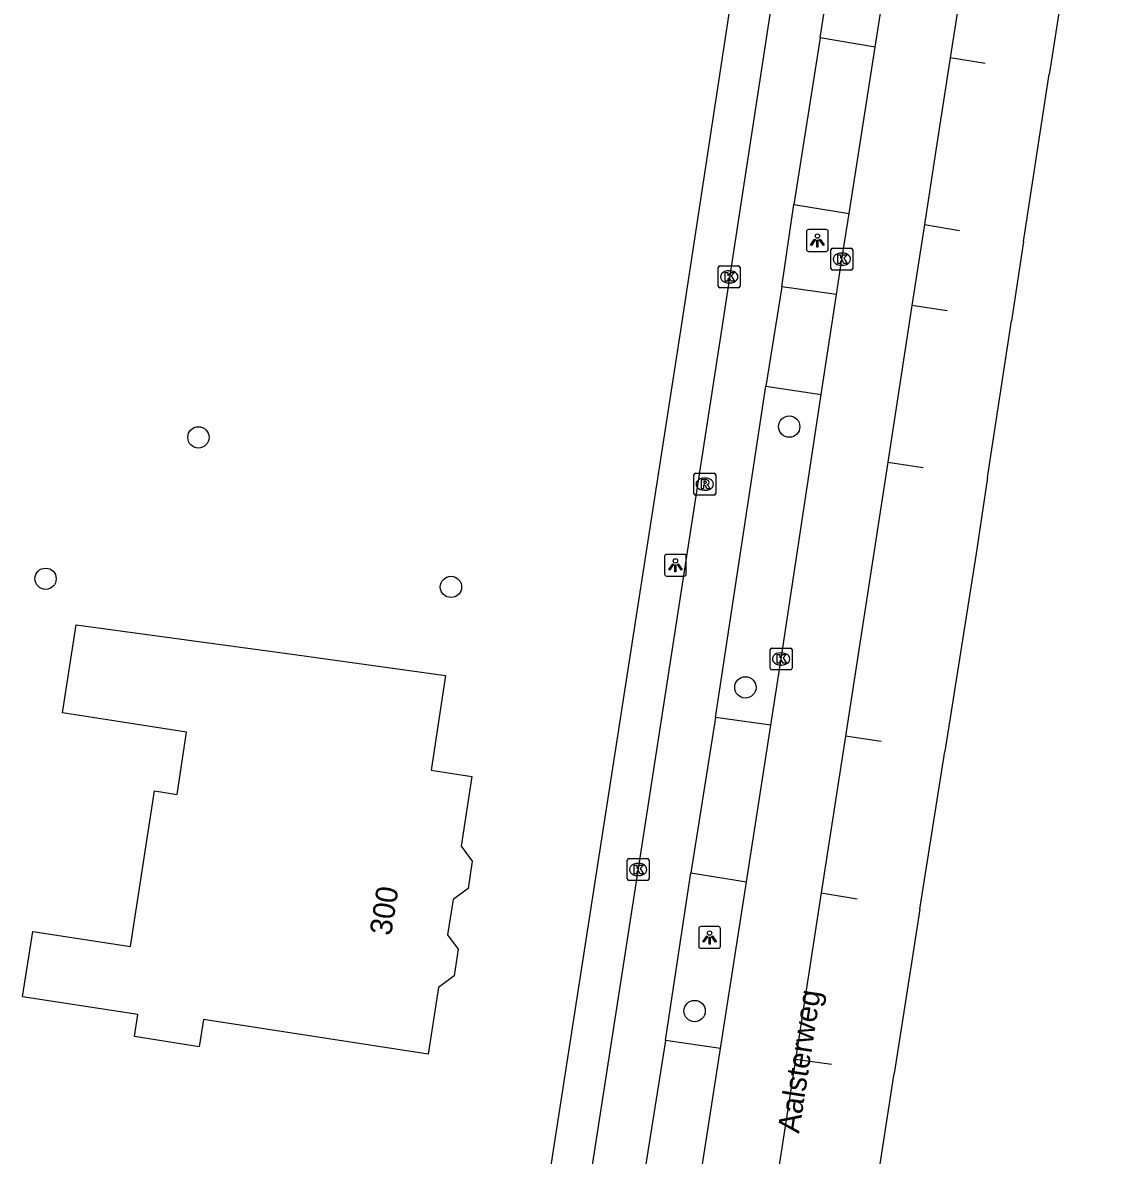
# Model space of a CAD drawing. Extents: x 161094 to 161705, y 379509 to 380907.
# Drawn here: x 161629.9 to 161680.5, y 380637.7 to 380689.7 of the extents above; entities that cross this region are included whole.
import ezdxf

# ---------------------------------------------------------------- set-up
doc = ezdxf.new("R2010")
doc.units = 0
for name, color, linetype in [('IMGEO_Boom', 7, 'Continuous'), ('IMGEO_Fietspad_gesloten', 7, 'Continuous'), ('IMGEO_Kolk', 7, 'Continuous'), ('IMGEO_Lichtpunt', 7, 'Continuous'), ('IMGEO_Openbare_ruimte_label', 7, 'Continuous'), ('IMGEO_OVBaan_gesloten', 7, 'Continuous'), ('IMGEO_Pand', 7, 'Continuous'), ('IMGEO_Pand_nummerreeks', 7, 'Continuous'), ('IMGEO_Rijbaan_lokaal_open', 7, 'Continuous'), ('IMGEO_Rijbaan_regionaal_gesloten', 7, 'Continuous'), ('IMGEO_Rioolput', 7, 'Continuous'), ('IMGEO_Voetpad_open', 7, 'Continuous')]:
    doc.layers.add(name, color=color, linetype=linetype)

msp = doc.modelspace()

# ---------------------------------------------------------------- linework, layer by layer
at = {"layer": 'IMGEO_Boom'}
for centre in [(161665.082, 380671.126), (161637.988, 380670.632), (161630.975, 380664.146), (161649.57, 380663.774), (161663.073, 380659.164), (161660.744, 380644.315)]:
    msp.add_circle(centre, 0.489, dxfattribs=at)
at = {"layer": 'IMGEO_Fietspad_gesloten'}
for points in [[(161669.451, 380724.595), (161665.616, 380699.327), (161661.966, 380675.456), (161658.261, 380651.539), (161654.372, 380626.519), (161650.679, 380602.47), (161649.98, 380598.059)], [(161666.5, 380688.955), (161668.286, 380700.544), (161669.904, 380711.432)], [(161664.743, 380677.545), (161665.3, 380681.309)], [(161661.709, 380657.778), (161664.016, 380672.987)], [(161659.406, 380642.973), (161660.571, 380650.65)]]:
    msp.add_lwpolyline(points, dxfattribs=at)
at = {"layer": 'IMGEO_Kolk'}
for p, q in [((161666.997, 380678.381), (161666.997, 380679.233)), ((161667.072, 380679.307), (161667.924, 380679.307)), ((161667.485, 380679.087), (161667.51, 380679.087)), ((161667.998, 380679.233), (161667.998, 380678.381)), ((161661.906, 380678.494), (161662.758, 380678.494)), ((161667.508, 380678.527), (161667.483, 380678.527)), ((161661.831, 380677.568), (161661.831, 380678.42)), ((161662.319, 380678.274), (161662.344, 380678.274)), ((161662.832, 380678.42), (161662.832, 380677.568)), ((161667.924, 380678.307), (161667.072, 380678.307)), ((161662.758, 380677.494), (161661.906, 380677.494)), ((161662.342, 380677.714), (161662.317, 380677.714)), ((161664.211, 380660.043), (161664.211, 380660.895)), ((161664.286, 380660.969), (161665.138, 380660.969)), ((161665.212, 380660.895), (161665.212, 380660.043)), ((161664.699, 380660.749), (161664.724, 380660.749)), ((161665.138, 380659.969), (161664.286, 380659.969)), ((161664.722, 380660.189), (161664.697, 380660.189)), ((161657.654, 380650.383), (161657.654, 380651.235)), ((161657.729, 380651.309), (161658.581, 380651.309)), ((161658.142, 380651.089), (161658.167, 380651.089)), ((161658.655, 380651.235), (161658.655, 380650.383)), ((161658.165, 380650.529), (161658.14, 380650.529)), ((161658.581, 380650.309), (161657.729, 380650.309))]:
    msp.add_line(p, q, dxfattribs=at)
for points in [[(161666.997, 380678.381), (161666.997, 380679.233)], [(161667.072, 380679.307), (161667.924, 380679.307)], [(161667.318, 380679.007), (161667.441, 380679.007), (161667.441, 380678.856), (161667.571, 380679.007), (161667.735, 380679.007), (161667.589, 380678.856), (161667.742, 380678.607), (161667.59, 380678.607), (161667.505, 380678.771), (161667.441, 380678.704), (161667.441, 380678.607), (161667.318, 380678.607), (161667.318, 380679.007)], [(161667.998, 380679.233), (161667.998, 380678.381)], [(161661.906, 380678.494), (161662.758, 380678.494)], [(161661.831, 380677.568), (161661.831, 380678.42)], [(161662.152, 380678.194), (161662.275, 380678.194), (161662.275, 380678.043), (161662.405, 380678.194), (161662.569, 380678.194), (161662.423, 380678.043), (161662.576, 380677.794), (161662.424, 380677.794), (161662.339, 380677.958), (161662.275, 380677.891), (161662.275, 380677.794), (161662.152, 380677.794), (161662.152, 380678.194)], [(161662.832, 380678.42), (161662.832, 380677.568)], [(161667.924, 380678.307), (161667.072, 380678.307)], [(161662.758, 380677.494), (161661.906, 380677.494)], [(161664.211, 380660.043), (161664.211, 380660.895)], [(161664.286, 380660.969), (161665.138, 380660.969)], [(161665.212, 380660.895), (161665.212, 380660.043)], [(161664.532, 380660.669), (161664.655, 380660.669), (161664.655, 380660.518), (161664.785, 380660.669), (161664.949, 380660.669), (161664.803, 380660.518), (161664.956, 380660.269), (161664.804, 380660.269), (161664.719, 380660.433), (161664.655, 380660.366), (161664.655, 380660.269), (161664.532, 380660.269), (161664.532, 380660.669)], [(161665.138, 380659.969), (161664.286, 380659.969)], [(161657.654, 380650.383), (161657.654, 380651.235)], [(161657.729, 380651.309), (161658.581, 380651.309)], [(161657.975, 380651.009), (161658.098, 380651.009), (161658.098, 380650.858), (161658.228, 380651.009), (161658.392, 380651.009), (161658.246, 380650.858), (161658.399, 380650.609), (161658.247, 380650.609), (161658.162, 380650.773), (161658.098, 380650.706), (161658.098, 380650.609), (161657.975, 380650.609), (161657.975, 380651.009)], [(161658.655, 380651.235), (161658.655, 380650.383)], [(161658.581, 380650.309), (161657.729, 380650.309)]]:
    msp.add_lwpolyline(points, dxfattribs=at)
for centre, start, end in [((161667.074, 380679.231), 91.552, 178.448), ((161667.074, 380679.231), 91.552, 178.448), ((161667.922, 380679.231), 1.552, 88.448), ((161667.922, 380679.231), 1.552, 88.448), ((161661.908, 380678.418), 91.552, 178.448), ((161661.908, 380678.418), 91.552, 178.448), ((161662.756, 380678.418), 1.552, 88.448), ((161662.756, 380678.418), 1.552, 88.448), ((161667.074, 380678.383), 181.552, 268.448), ((161667.074, 380678.383), 181.552, 268.448), ((161667.922, 380678.383), 271.552, 358.448), ((161667.922, 380678.383), 271.552, 358.448), ((161661.908, 380677.57), 181.552, 268.448), ((161661.908, 380677.57), 181.552, 268.448), ((161662.756, 380677.57), 271.552, 358.448), ((161662.756, 380677.57), 271.552, 358.448), ((161664.288, 380660.893), 91.552, 178.448), ((161664.288, 380660.893), 91.552, 178.448), ((161665.136, 380660.893), 1.552, 88.448), ((161665.136, 380660.893), 1.552, 88.448), ((161664.288, 380660.045), 181.552, 268.448), ((161664.288, 380660.045), 181.552, 268.448), ((161665.136, 380660.045), 271.552, 358.448), ((161665.136, 380660.045), 271.552, 358.448), ((161657.731, 380651.233), 91.552, 178.448), ((161657.731, 380651.233), 91.552, 178.448), ((161658.579, 380651.233), 1.552, 88.448), ((161658.579, 380651.233), 1.552, 88.448), ((161657.731, 380650.385), 181.552, 268.448), ((161657.731, 380650.385), 181.552, 268.448), ((161658.579, 380650.385), 271.552, 358.448), ((161658.579, 380650.385), 271.552, 358.448)]:
    msp.add_arc(centre, 0.0765, start, end, dxfattribs=at)
for centre, major_axis, ratio, start_param, end_param in [((161667.484, 380678.807), (-0.387, 0.002), 0.722429, 4.712389, 7.853982), ((161667.509, 380678.807), (-0.39, 0.002), 0.717154, 1.570796, 4.712389), ((161662.318, 380677.994), (-0.387, 0.002), 0.722429, 4.712389, 7.853982), ((161662.343, 380677.994), (-0.39, 0.002), 0.717154, 1.570796, 4.712389), ((161664.698, 380660.469), (-0.387, 0.002), 0.722429, 4.712389, 7.853982), ((161664.723, 380660.469), (-0.39, 0.002), 0.717154, 1.570796, 4.712389), ((161658.141, 380650.809), (-0.387, 0.002), 0.722429, 4.712389, 7.853982), ((161658.166, 380650.809), (-0.39, 0.002), 0.717154, 1.570796, 4.712389)]:
    msp.add_ellipse(centre, major_axis=major_axis, ratio=ratio, start_param=start_param, end_param=end_param, dxfattribs=at)
at = {"layer": 'IMGEO_Lichtpunt'}
for p, q in [((161665.876, 380680.067), (161665.876, 380679.26)), ((161665.876, 380680.067), (161665.876, 380679.26)), ((161666.778, 380680.162), (161665.97, 380680.162)), ((161666.778, 380680.162), (161665.97, 380680.162)), ((161666.872, 380679.26), (161666.872, 380680.067)), ((161666.872, 380679.26), (161666.872, 380680.067)), ((161665.97, 380679.166), (161666.778, 380679.166)), ((161665.97, 380679.166), (161666.778, 380679.166)), ((161659.367, 380665.171), (161659.367, 380664.364)), ((161659.367, 380665.171), (161659.367, 380664.364)), ((161660.269, 380665.266), (161659.461, 380665.266)), ((161660.269, 380665.266), (161659.461, 380665.266)), ((161660.363, 380664.364), (161660.363, 380665.171)), ((161660.363, 380664.364), (161660.363, 380665.171)), ((161659.461, 380664.27), (161660.269, 380664.27)), ((161659.461, 380664.27), (161660.269, 380664.27)), ((161660.934, 380648.097), (161660.934, 380647.29)), ((161660.934, 380648.097), (161660.934, 380647.29)), ((161661.836, 380648.192), (161661.028, 380648.192)), ((161661.836, 380648.192), (161661.028, 380648.192)), ((161661.93, 380647.29), (161661.93, 380648.097)), ((161661.93, 380647.29), (161661.93, 380648.097)), ((161661.028, 380647.196), (161661.836, 380647.196)), ((161661.028, 380647.196), (161661.836, 380647.196))]:
    msp.add_line(p, q, dxfattribs=at)
for points in [[(161666.25, 380679.731), (161666.289, 380679.703), (161666.101, 380679.441), (161666.063, 380679.468), (161666.25, 380679.731)], [(161666.352, 380679.683), (161666.399, 380679.683), (161666.399, 380679.361), (161666.352, 380679.361), (161666.352, 380679.683)], [(161666.462, 380679.703), (161666.5, 380679.73), (161666.687, 380679.468), (161666.648, 380679.44), (161666.462, 380679.703)], [(161659.741, 380664.835), (161659.78, 380664.807), (161659.592, 380664.545), (161659.554, 380664.572), (161659.741, 380664.835)], [(161659.843, 380664.787), (161659.89, 380664.787), (161659.89, 380664.465), (161659.843, 380664.465), (161659.843, 380664.787)], [(161659.953, 380664.807), (161659.991, 380664.834), (161660.178, 380664.572), (161660.139, 380664.544), (161659.953, 380664.807)], [(161661.308, 380647.761), (161661.347, 380647.733), (161661.159, 380647.471), (161661.121, 380647.498), (161661.308, 380647.761)], [(161661.41, 380647.713), (161661.457, 380647.713), (161661.457, 380647.391), (161661.41, 380647.391), (161661.41, 380647.713)], [(161661.52, 380647.733), (161661.558, 380647.76), (161661.745, 380647.498), (161661.706, 380647.47), (161661.52, 380647.733)]]:
    msp.add_lwpolyline(points, dxfattribs=at)
for centre in [(161666.375, 380679.865), (161659.866, 380664.969), (161661.433, 380647.895)]:
    msp.add_circle(centre, 0.0994, dxfattribs=at)
for centre, start, end in [((161665.97, 380680.067), 90, 180), ((161665.97, 380680.067), 90, 180), ((161666.778, 380680.067), 0, 90), ((161666.778, 380680.067), 0, 90), ((161665.97, 380679.26), 180, 270), ((161665.97, 380679.26), 180, 270), ((161666.778, 380679.26), 270, 0), ((161666.778, 380679.26), 270, 360), ((161659.461, 380665.171), 90, 180), ((161659.461, 380665.171), 90, 180), ((161660.269, 380665.171), 0, 90), ((161660.269, 380665.171), 0, 90), ((161659.461, 380664.364), 180, 270), ((161659.461, 380664.364), 180, 270), ((161660.269, 380664.364), 270, 0), ((161660.269, 380664.364), 270, 360), ((161661.028, 380648.097), 90, 180), ((161661.028, 380648.097), 90, 180), ((161661.836, 380648.097), 0, 90), ((161661.836, 380648.097), 0, 90), ((161661.028, 380647.29), 180, 270), ((161661.028, 380647.29), 180, 270), ((161661.836, 380647.29), 270, 0), ((161661.836, 380647.29), 270, 360)]:
    msp.add_arc(centre, 0.0946, start, end, dxfattribs=at)
at = {"layer": 'IMGEO_OVBaan_gesloten'}
for points in [[(161669.019, 380688.526), (161670.427, 380697.518), (161672.445, 380710.552), (161672.52, 380711.039)], [(161675.998, 380710.509), (161672.472, 380688.045)], [(161667.825, 380680.896), (161669.019, 380688.526)], [(161672.472, 380688.045), (161671.791, 380683.706), (161671.28, 380680.392)], [(161667.252, 380677.192), (161667.498, 380678.807), (161667.825, 380680.896)], [(161671.28, 380680.392), (161670.707, 380676.68)], [(161666.554, 380672.596), (161667.252, 380677.192)], [(161670.707, 380676.68), (161669.599, 380669.492)], [(161664.239, 380657.43), (161664.712, 380660.469), (161666.554, 380672.596)], [(161669.599, 380669.492), (161667.662, 380656.934)], [(161663.121, 380650.24), (161664.239, 380657.43)], [(161667.662, 380656.934), (161666.553, 380649.746)], [(161661.933, 380642.604), (161663.121, 380650.24)], [(161666.553, 380649.746), (161665.372, 380642.089)], [(161660.816, 380635.426), (161661.933, 380642.604)], [(161665.372, 380642.089), (161664.444, 380636.071), (161664.26, 380634.896)]]:
    msp.add_lwpolyline(points, dxfattribs=at)
at = {"layer": 'IMGEO_Pand'}
msp.add_lwpolyline([(161649.322, 380659.715), (161648.655, 380655.372), (161650.529, 380655.083), (161650.036, 380651.883), (161650.545, 380651.187), (161650.354, 380649.942), (161649.665, 380649.437), (161649.415, 380647.817), (161649.903, 380647.152), (161649.715, 380645.932), (161648.993, 380645.403), (161648.522, 380642.339), (161638.217, 380643.927), (161638.024, 380642.67), (161635.055, 380643.142), (161635.212, 380644.156), (161629.925, 380644.97), (161630.387, 380647.963), (161634.872, 380647.273), (161635.971, 380654.413), (161637.004, 380654.254), (161637.446, 380657.117), (161631.756, 380658.002), (161632.375, 380662.033), (161637.446, 380661.341), (161642.4, 380660.665), (161649.322, 380659.715)], dxfattribs=at)
at = {"layer": 'IMGEO_Rijbaan_lokaal_open'}
for points in [[(161666.5, 380688.955), (161665.3, 380681.309)], [(161669.019, 380688.526), (161666.5, 380688.955)], [(161674.066, 380687.78), (161672.472, 380688.045)], [(161665.3, 380681.309), (161667.825, 380680.896)], [(161671.28, 380680.392), (161672.892, 380680.117)], [(161664.743, 380677.545), (161664.016, 380672.987)], [(161667.252, 380677.192), (161664.743, 380677.545)], [(161672.326, 380676.43), (161670.707, 380676.68)], [(161664.016, 380672.987), (161666.554, 380672.596)], [(161669.599, 380669.492), (161671.225, 380669.246)], [(161661.709, 380657.778), (161660.571, 380650.65)], [(161664.239, 380657.43), (161661.709, 380657.778)], [(161669.298, 380656.679), (161667.662, 380656.934)], [(161660.571, 380650.65), (161663.121, 380650.24)], [(161666.553, 380649.746), (161668.194, 380649.472)], [(161659.406, 380642.973), (161658.274, 380635.854)], [(161661.933, 380642.604), (161659.406, 380642.973)], [(161667.027, 380641.859), (161665.372, 380642.089)]]:
    msp.add_lwpolyline(points, dxfattribs=at)
at = {"layer": 'IMGEO_Rijbaan_regionaal_gesloten'}
for points in [[(161680.499, 380709.768), (161679.9, 380705.885), (161677.062, 380687.652), (161677.007, 380687.29)], [(161675.835, 380679.616), (161677.007, 380687.29)], [(161675.835, 380679.616), (161675.279, 380675.974)], [(161674.184, 380668.798), (161675.279, 380675.974)], [(161674.184, 380668.798), (161673.65, 380665.298), (161672.217, 380656.223)], [(161671.075, 380648.991), (161672.217, 380656.223)], [(161671.075, 380648.991), (161670.61, 380646.045), (161669.899, 380641.459)], [(161668.766, 380634.148), (161669.899, 380641.459)]]:
    msp.add_lwpolyline(points, dxfattribs=at)
at = {"layer": 'IMGEO_Rioolput'}
for p, q in [((161660.709, 380668.062), (161660.709, 380668.914)), ((161660.784, 380668.988), (161661.636, 380668.988)), ((161661.197, 380668.768), (161661.222, 380668.768)), ((161661.71, 380668.914), (161661.71, 380668.062)), ((161661.22, 380668.208), (161661.195, 380668.208)), ((161661.636, 380667.988), (161660.784, 380667.988))]:
    msp.add_line(p, q, dxfattribs=at)
for points in [[(161660.709, 380668.062), (161660.709, 380668.914)], [(161660.784, 380668.988), (161661.636, 380668.988)], [(161661.298, 380668.686), (161661.046, 380668.688), (161661.046, 380668.288)], [(161661.224, 380668.607), (161661.17, 380668.607), (161661.17, 380668.526)], [(161661.71, 380668.914), (161661.71, 380668.062)], [(161661.046, 380668.288), (161661.17, 380668.288), (161661.17, 380668.45), (161661.181, 380668.45)], [(161661.17, 380668.526), (161661.222, 380668.526)], [(161661.228, 380668.421), (161661.299, 380668.288), (161661.439, 380668.288), (161661.374, 380668.414)], [(161661.636, 380667.988), (161660.784, 380667.988)]]:
    msp.add_lwpolyline(points, dxfattribs=at)
for centre, radius, start, end in [((161660.786, 380668.912), 0.0765, 91.552, 178.448), ((161660.786, 380668.912), 0.0765, 91.552, 178.448), ((161661.23, 380668.511), 0.0964, 77.0061, 93.1865), ((161661.244, 380668.568), 0.0378, 276.6634, 79.6772), ((161661.297, 380668.576), 0.109, 350.3612, 89.416), ((161661.295, 380668.576), 0.112, 277.5842, 350.9817), ((161661.634, 380668.912), 0.0765, 1.552, 88.448), ((161661.634, 380668.912), 0.0765, 1.552, 88.448), ((161660.786, 380668.064), 0.0765, 181.552, 268.448), ((161660.786, 380668.064), 0.0765, 181.552, 268.448), ((161661.18, 380668.397), 0.0533, 26.0293, 88.6989), ((161661.206, 380668.715), 0.19, 274.7715, 282.9687), ((161661.279, 380668.361), 0.108, 29.5134, 73.7905), ((161661.634, 380668.064), 0.0765, 271.552, 358.448), ((161661.634, 380668.064), 0.0765, 271.552, 358.448)]:
    msp.add_arc(centre, radius, start, end, dxfattribs=at)
for centre, major_axis, ratio, start_param, end_param in [((161661.196, 380668.488), (-0.387, 0.002), 0.722429, 4.712389, 7.853982), ((161661.221, 380668.488), (-0.39, 0.002), 0.717154, 1.570796, 4.712389)]:
    msp.add_ellipse(centre, major_axis=major_axis, ratio=ratio, start_param=start_param, end_param=end_param, dxfattribs=at)
at = {"layer": 'IMGEO_Voetpad_open'}
msp.add_lwpolyline([(161650.471, 380613.456), (161652.544, 380626.803), (161656.433, 380651.823), (161660.137, 380675.736), (161663.788, 380699.607), (161666.443, 380717.104), (161666.62, 380718.244), (161666.757, 380720.007), (161666.844, 380720.867), (161667.392, 380724.357)], dxfattribs=at)

# ---------------------------------------------------------------- texts
at = {"layer": 'IMGEO_Openbare_ruimte_label'}
msp.add_text('Aalsterweg', height=1, rotation=81.3191, dxfattribs=at).set_placement((161665.533, 380638.677))
at = {"layer": 'IMGEO_Pand_nummerreeks'}
msp.add_text('300', height=1, rotation=81.0506, dxfattribs=at).set_placement((161646.822, 380647.744))

doc.saveas('drawing.dxf')
